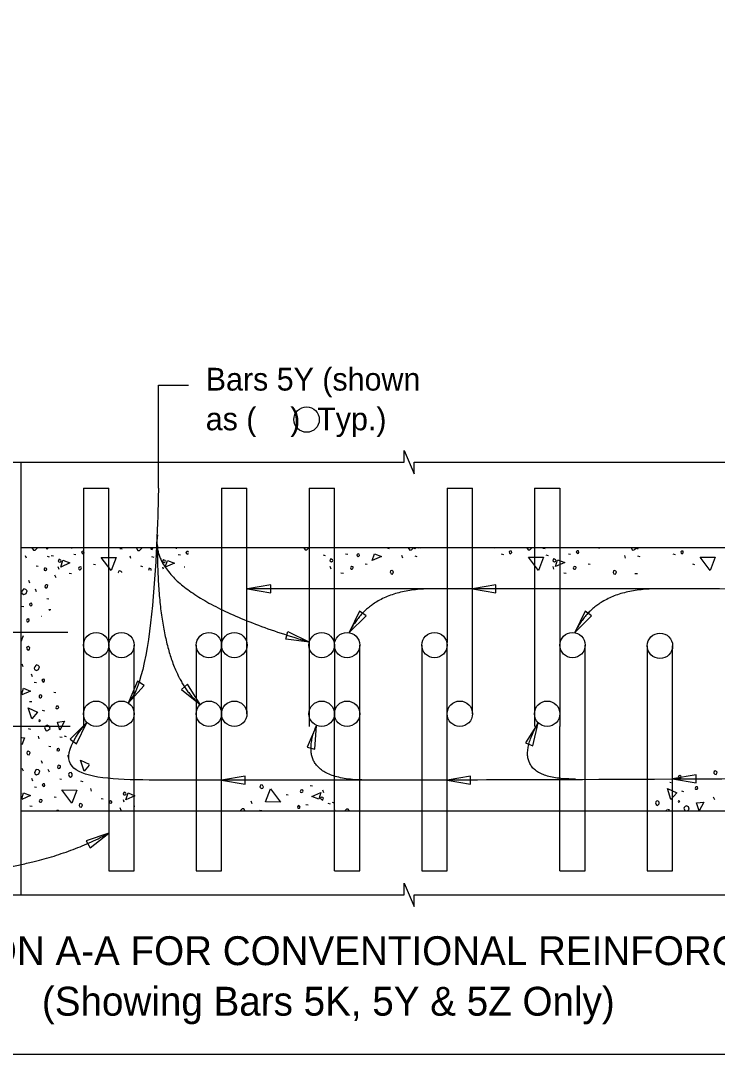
# Model space of a CAD drawing. Extents: x -21.7 to 40.7, y -0.2 to 17.4.
# Drawn here: x 6.2 to 9.289, y 3.607 to 8.188 of the extents above; entities that cross this region are included whole.
import ezdxf

# ---------------------------------------------------------------- set-up
doc = ezdxf.new("R2010")
doc.units = 0
for name, color, linetype in [('ActivePts-ConstElements', 7, 'Continuous'), ('AdhocPoint_dp', 7, 'Continuous'), ('Border', 7, 'Continuous'), ('Patterning', 7, 'Continuous'), ('PlotBorder_dp', 7, 'Continuous'), ('SheetBorder_dp', 7, 'Continuous')]:
    doc.layers.add(name, color=color, linetype=linetype)

msp = doc.modelspace()

# ---------------------------------------------------------------- linework, layer by layer
at = {"layer": 'ActivePts-ConstElements'}
msp.add_lwpolyline([(4.6468, 3.607), (25.1721, 3.607), (25.1721, 16.5801), (4.6468, 16.5801)], close=True, dxfattribs=at)
at = {"layer": 'AdhocPoint_dp'}
for p, q in [((6.4086, 5.477), (6.001, 5.477)), ((6.4188, 5.0603), (5.4676, 5.0603))]:
    msp.add_line(p, q, dxfattribs=at)
for points in [[(6.8108, 6.1166), (6.8108, 6.5728), (6.9439, 6.5728)], [(6.0632, 6.2313), (7.9006, 6.2313), (7.9006, 6.283), (7.9231, 6.2313), (7.9456, 6.1796), (7.9456, 6.2313), (9.8737, 6.2313)], [(6.0632, 4.3145), (7.9006, 4.3145), (7.9006, 4.3662), (7.9231, 4.3145), (7.9456, 4.2629), (7.9456, 4.3145), (9.8737, 4.3145)]]:
    msp.add_lwpolyline(points, dxfattribs=at)
for points in [[(7.2052, 5.6701), (7.3093, 5.6524), (7.3093, 5.6877)], [(8.2036, 5.6701), (8.3078, 5.6524), (8.3078, 5.6877)], [(7.6572, 5.4761), (7.7319, 5.5508), (7.7032, 5.5712)], [(8.6572, 5.476), (8.7319, 5.5507), (8.7032, 5.5711)], [(7.3853, 5.4807), (7.4803, 5.4345), (7.3754, 5.4468)], [(6.6764, 5.1641), (6.7477, 5.242), (6.7181, 5.2611)], [(6.9959, 5.1582), (6.9402, 5.2479), (6.9137, 5.2246)], [(6.4937, 5.078), (6.4188, 5.0036), (6.4475, 4.983)], [(7.5118, 5.0652), (7.47, 4.9683), (7.5043, 4.9599)], [(8.4952, 5.0766), (8.4391, 4.9872), (8.4717, 4.9737)], [(7.0912, 4.8226), (7.1953, 4.8049), (7.1953, 4.8402)], [(8.0911, 4.8226), (8.1952, 4.8049), (8.1952, 4.8402)], [(9.091, 4.8281), (9.1952, 4.8104), (9.1952, 4.8457)], [(6.5911, 4.5872), (6.4911, 4.5533), (6.5078, 4.5223)]]:
    msp.add_lwpolyline(points, close=True, dxfattribs=at)
for points, degree in [([(6.8108, 6.1166), (6.8082, 5.99), (6.7969, 5.2786), (6.6768, 5.1645)], 3), ([(6.807, 5.909), (6.7619, 5.6447), (7.4803, 5.4345)], 2), ([(6.8062, 5.8611), (6.8051, 5.3098), (6.9959, 5.1582)], 2), ([(9.9351, 5.669), (8.6633, 5.6701), (8.232, 5.6701), (7.2052, 5.6701)], 3), ([(8.0247, 5.6701), (7.7495, 5.6706), (7.6572, 5.4761)], 2), ([(9.0247, 5.6701), (8.7495, 5.6706), (8.6572, 5.476)], 2), ([(9.9425, 4.8297), (8.3909, 4.8226), (7.9981, 4.8226), (6.7858, 4.8226), (6.2772, 4.8226), (6.4937, 5.078)], 3), ([(7.7347, 4.8226), (7.4098, 4.8226), (7.5118, 5.0652)], 2), ([(8.6602, 4.8271), (8.3476, 4.8233), (8.4952, 5.0766)], 2), ([(5.776, 4.4087), (6.2517, 4.4054), (6.5911, 4.5872)], 2)]:
    msp.add_open_spline(points, degree=degree, dxfattribs=at)
at = {"layer": 'Border'}
for p, q in [((6.3355, 5.8186), (6.345, 5.8163)), ((6.4281, 5.8487), (6.4272, 5.8511)), ((6.4351, 5.824), (6.4451, 5.8222)), ((6.6396, 5.8493), (6.6496, 5.8476)), ((6.8911, 5.8475), (6.8904, 5.8495)), ((6.8982, 5.8228), (6.9082, 5.821)), ((7.5408, 5.8205), (7.5503, 5.8182)), ((7.6404, 5.8259), (7.6504, 5.8241)), ((7.8248, 5.8512), (7.8348, 5.8494)), ((8.3037, 5.8494), (8.3028, 5.852)), ((8.3308, 5.8247), (8.3408, 5.8229)), ((8.5153, 5.85), (8.5253, 5.8483)), ((8.5293, 5.8205), (8.5388, 5.8182)), ((8.6289, 5.8259), (8.6389, 5.8241)), ((8.7668, 5.8482), (8.7654, 5.852)), ((9.092, 5.8247), (9.102, 5.8229)), ((6.226, 5.8057), (6.2219, 5.8169)), ((6.2684, 5.7727), (6.2772, 5.771)), ((6.3173, 5.8146), (6.3267, 5.8122)), ((6.5229, 5.7798), (6.5317, 5.778)), ((6.6891, 5.8045), (6.6849, 5.8157)), ((6.7804, 5.8134), (6.7898, 5.811)), ((6.7986, 5.8175), (6.8081, 5.8151)), ((7.7282, 5.7817), (7.737, 5.7799)), ((7.8943, 5.8064), (7.8902, 5.8176)), ((7.9472, 5.8164), (7.9566, 5.8141)), ((8.7167, 5.7817), (8.7255, 5.7799)), ((8.8828, 5.8064), (8.8787, 5.8176)), ((8.9357, 5.8164), (8.9451, 5.8141)), ((9.1798, 5.7805), (9.1886, 5.7787)), ((6.3568, 5.7197), (6.352, 5.7315)), ((6.3709, 5.7563), (6.3668, 5.7675)), ((6.4151, 5.7391), (6.4257, 5.738)), ((6.7315, 5.7715), (6.7403, 5.7698)), ((6.8329, 5.7579), (6.8299, 5.7663)), ((7.5762, 5.7581), (7.5721, 5.7693)), ((7.6203, 5.741), (7.6309, 5.7398)), ((8.5647, 5.7581), (8.5606, 5.7693)), ((8.6088, 5.741), (8.6194, 5.7398)), ((8.9241, 5.7387), (8.9347, 5.7375)), ((6.2407, 5.6955), (6.236, 5.7073)), ((6.2707, 5.6573), (6.266, 5.669)), ((6.2041, 5.593), (6.2142, 5.5913)), ((6.3167, 5.6278), (6.3249, 5.6266)), ((6.2919, 5.5488), (6.2937, 5.5485)), ((6.2108, 5.3251), (6.2061, 5.3369)), ((6.2526, 5.2809), (6.2485, 5.2921)), ((6.2596, 5.2562), (6.2697, 5.2544)), ((6.3474, 5.212), (6.3563, 5.2102)), ((6.2396, 5.1714), (6.2502, 5.1702)), ((6.2956, 5.1319), (6.305, 5.1295)), ((6.2332, 5.0506), (6.2432, 5.0488)), ((6.2827, 5.0058), (6.2785, 5.017)), ((6.374, 5.0146), (6.3834, 5.0123)), ((6.3922, 5.0187), (6.4016, 5.0164)), ((6.3251, 4.9728), (6.3339, 4.971)), ((6.2974, 4.8956), (6.2927, 4.9074)), ((6.4134, 4.9198), (6.4087, 4.9316)), ((6.2119, 4.862), (6.2072, 4.8738)), ((6.3274, 4.8574), (6.3227, 4.8691)), ((6.2538, 4.8178), (6.2497, 4.829)), ((6.3734, 4.8279), (6.3816, 4.8267)), ((6.4653, 4.8185), (6.4753, 4.8167)), ((9.0784, 4.8132), (9.0849, 4.8125)), ((6.2608, 4.7931), (6.2708, 4.7914)), ((6.5148, 4.7737), (6.5107, 4.7849)), ((7.4942, 4.7959), (7.4836, 4.7971)), ((7.5384, 4.7788), (7.5425, 4.7676)), ((9.1303, 4.7742), (9.1397, 4.7718)), ((6.3486, 4.7489), (6.3575, 4.7472)), ((6.5572, 4.7407), (6.5661, 4.7389)), ((6.6597, 4.7242), (6.6556, 4.7354)), ((7.2202, 4.7305), (7.2244, 4.7193)), ((7.3864, 4.7553), (7.3776, 4.757)), ((7.592, 4.7205), (7.5826, 4.7229)), ((9.2776, 4.7353), (9.2729, 4.7471)), ((6.2408, 4.7083), (6.2514, 4.7071)), ((6.6456, 4.6877), (6.6409, 4.6995)), ((6.7039, 4.7071), (6.7064, 4.7068)), ((7.2697, 4.6857), (7.2597, 4.6875)), ((7.4742, 4.7111), (7.4642, 4.7129)), ((7.4812, 4.6864), (7.4818, 4.685)), ((7.5738, 4.7164), (7.5643, 4.7188)), ((9.0678, 4.6929), (9.0778, 4.6911))]:
    msp.add_line(p, q, dxfattribs=at)
for points in [[(6.25, 5.8518), (6.2566, 5.8411), (6.2643, 5.8417), (6.2672, 5.8446), (6.2737, 5.8511), (6.2735, 5.8517)], [(6.3173, 5.844), (6.3148, 5.8516)], [(6.3212, 5.8515), (6.3173, 5.844)], [(6.4722, 5.8281), (6.4758, 5.8246), (6.4793, 5.8269), (6.4816, 5.8305), (6.4805, 5.8364), (6.4775, 5.8369), (6.4734, 5.8364), (6.4699, 5.8328), (6.4722, 5.8281)], [(6.7134, 5.8501), (6.7197, 5.8399), (6.7274, 5.8405), (6.7303, 5.8434), (6.7368, 5.8499), (6.7367, 5.85)], [(6.7804, 5.8428), (6.7781, 5.8499)], [(6.784, 5.8499), (6.7804, 5.8428)], [(6.9444, 5.8309), (6.9435, 5.8352), (6.9406, 5.8358), (6.9365, 5.8352), (6.9329, 5.8316), (6.9353, 5.8269)], [(6.9353, 5.8269), (6.9388, 5.8234), (6.9424, 5.8258), (6.9437, 5.8278)], [(7.4563, 5.852), (7.4619, 5.843), (7.4696, 5.8435), (7.4725, 5.8465), (7.478, 5.852)], [(7.6927, 5.8163), (7.6962, 5.8127), (7.6998, 5.8151), (7.7021, 5.8186), (7.7009, 5.8245), (7.698, 5.8251), (7.6939, 5.8245), (7.6903, 5.821), (7.6927, 5.8163)], [(7.7593, 5.7952), (7.7688, 5.8259), (7.8, 5.8135), (7.7593, 5.7952)], [(7.9187, 5.852), (7.925, 5.8418), (7.9326, 5.8424), (7.9356, 5.8453), (7.9421, 5.8518), (7.942, 5.852)], [(7.9472, 5.8459), (7.9452, 5.852)], [(7.9503, 5.852), (7.9472, 5.8459)], [(7.9635, 5.8511), (7.9633, 5.852)], [(7.9694, 5.852), (7.9681, 5.8494)], [(8.3679, 5.8288), (8.3715, 5.8253), (8.375, 5.8276), (8.3774, 5.8312), (8.3762, 5.8371), (8.3732, 5.8376), (8.3691, 5.8371), (8.3656, 5.8335), (8.3679, 5.8288)], [(8.4448, 5.852), (8.4504, 5.843), (8.4581, 5.8435), (8.461, 5.8465), (8.4665, 5.852)], [(8.666, 5.83), (8.6695, 5.8265), (8.6731, 5.8288), (8.6754, 5.8323), (8.6742, 5.8382), (8.6713, 5.8388), (8.6672, 5.8382), (8.6636, 5.8347), (8.666, 5.83)], [(8.9072, 5.852), (8.9135, 5.8418), (8.9211, 5.8424), (8.9241, 5.8453), (8.9306, 5.8518), (8.9305, 5.852)], [(8.9357, 5.8459), (8.9337, 5.852)], [(8.9388, 5.852), (8.9357, 5.8459)], [(9.1291, 5.8288), (9.1326, 5.8253), (9.1361, 5.8276), (9.1385, 5.8312), (9.1373, 5.8371), (9.1344, 5.8376), (9.1303, 5.8371), (9.1267, 5.8335), (9.1291, 5.8288)], [(6.3697, 5.7892), (6.3738, 5.7886), (6.378, 5.7904), (6.3792, 5.7939), (6.3774, 5.7968), (6.3738, 5.7992), (6.3697, 5.801), (6.3674, 5.7963), (6.3662, 5.7927), (6.3697, 5.7892)], [(6.3779, 5.7668), (6.3874, 5.7975), (6.4186, 5.7851), (6.3779, 5.7668)], [(6.6013, 5.7509), (6.5565, 5.8098), (6.6231, 5.8093), (6.6013, 5.7509)], [(6.8328, 5.788), (6.8369, 5.7874), (6.8411, 5.7892), (6.8422, 5.7927), (6.8405, 5.7957), (6.8369, 5.798), (6.8328, 5.7998), (6.8304, 5.7951), (6.8293, 5.7915), (6.8328, 5.788)], [(6.841, 5.7656), (6.8504, 5.7963), (6.8817, 5.7839), (6.841, 5.7656)], [(7.575, 5.7911), (7.5791, 5.7905), (7.5833, 5.7922), (7.5844, 5.7958), (7.5827, 5.7987), (7.5791, 5.8011), (7.575, 5.8028), (7.5726, 5.7981), (7.5715, 5.7946), (7.575, 5.7911)], [(8.497, 5.7516), (8.4522, 5.8105), (8.5188, 5.81), (8.497, 5.7516)], [(8.5635, 5.7911), (8.5676, 5.7905), (8.5718, 5.7922), (8.5729, 5.7958), (8.5712, 5.7987), (8.5676, 5.8011), (8.5635, 5.8028), (8.5611, 5.7981), (8.56, 5.7946), (8.5635, 5.7911)], [(8.5717, 5.7687), (8.5811, 5.7993), (8.6124, 5.787), (8.5717, 5.7687)], [(9.2581, 5.7516), (9.2133, 5.8105), (9.2799, 5.81), (9.2581, 5.7516)], [(6.3044, 5.7533), (6.3108, 5.7515), (6.315, 5.7545), (6.3155, 5.7586), (6.3144, 5.7598), (6.3097, 5.7621), (6.3055, 5.7615), (6.3049, 5.7574), (6.3044, 5.7533)], [(6.4604, 5.755), (6.4628, 5.755), (6.4675, 5.7574), (6.4693, 5.7627), (6.4687, 5.7656), (6.464, 5.768), (6.4581, 5.7645), (6.4569, 5.7609), (6.4581, 5.7574), (6.4604, 5.755)], [(6.6479, 5.7419), (6.6484, 5.7438), (6.6455, 5.7468), (6.6402, 5.7497), (6.6349, 5.748), (6.6331, 5.7427), (6.6341, 5.7407)], [(6.7779, 5.7531), (6.778, 5.7533), (6.7786, 5.7574), (6.7775, 5.7586), (6.7727, 5.7609), (6.7686, 5.7603), (6.768, 5.7562), (6.7675, 5.7522)], [(6.9283, 5.7662), (6.927, 5.7668), (6.9256, 5.766)], [(7.6657, 5.7569), (7.6681, 5.7569), (7.6728, 5.7593), (7.6745, 5.7646), (7.674, 5.7675), (7.6692, 5.7699), (7.6634, 5.7663), (7.6622, 5.7628), (7.6634, 5.7593), (7.6657, 5.7569)], [(7.8395, 5.7422), (7.8425, 5.7369), (7.8496, 5.7357), (7.8525, 5.741), (7.8537, 5.7457), (7.8507, 5.7487), (7.8454, 5.7516), (7.8401, 5.7498), (7.8384, 5.7445), (7.8395, 5.7422)], [(8.6542, 5.7569), (8.6566, 5.7569), (8.6613, 5.7593), (8.6631, 5.7646), (8.6625, 5.7675), (8.6577, 5.7699), (8.6519, 5.7663), (8.6507, 5.7628), (8.6519, 5.7593), (8.6542, 5.7569)], [(8.828, 5.7422), (8.831, 5.7369), (8.8381, 5.7357), (8.841, 5.741), (8.8422, 5.7457), (8.8392, 5.7487), (8.8339, 5.7516), (8.8286, 5.7498), (8.8269, 5.7445), (8.828, 5.7422)], [(6.3073, 5.6797), (6.3102, 5.6743), (6.3167, 5.6749), (6.3196, 5.6791), (6.3202, 5.6855), (6.3161, 5.6873), (6.3132, 5.6879), (6.3096, 5.6867), (6.3084, 5.6855), (6.3073, 5.6797)], [(6.2065, 5.6496), (6.2142, 5.6454), (6.2242, 5.6496), (6.2283, 5.6619), (6.2224, 5.6678), (6.2148, 5.6696), (6.2113, 5.6672), (6.2071, 5.6608), (6.2042, 5.6555), (6.2065, 5.6496)], [(6.2413, 5.5972), (6.2448, 5.5936), (6.2483, 5.596), (6.2507, 5.5995), (6.2495, 5.6054), (6.2466, 5.606), (6.2424, 5.6054), (6.2389, 5.6019), (6.2413, 5.5972)], [(6.3288, 5.5746), (6.3255, 5.5789), (6.3345, 5.5788)], [(6.2295, 5.5241), (6.2318, 5.5241), (6.2366, 5.5264), (6.2383, 5.5317), (6.2377, 5.5347), (6.233, 5.5371), (6.2271, 5.5335), (6.2259, 5.53), (6.2271, 5.5264), (6.2295, 5.5241)], [(6.2006, 5.4737), (6.2037, 5.4737)], [(6.2109, 5.4614), (6.2011, 5.4352)], [(6.2267, 5.4047), (6.2296, 5.3994), (6.2367, 5.3982), (6.2396, 5.4035), (6.2408, 5.4082), (6.2379, 5.4111), (6.2326, 5.4141), (6.2273, 5.4123), (6.2255, 5.407), (6.2267, 5.4047)], [(6.262, 5.3127), (6.2697, 5.3086), (6.2797, 5.3127), (6.2838, 5.3251), (6.2779, 5.331), (6.2703, 5.3328), (6.2667, 5.3304), (6.2626, 5.3239), (6.2597, 5.3186), (6.262, 5.3127)], [(6.2968, 5.2603), (6.3003, 5.2568), (6.3038, 5.2592), (6.3062, 5.2627), (6.305, 5.2686), (6.3021, 5.2692), (6.2979, 5.2686), (6.2944, 5.265), (6.2968, 5.2603)], [(6.2045, 5.2055), (6.2119, 5.2297), (6.2431, 5.2173), (6.2046, 5.2)], [(6.285, 5.1873), (6.2873, 5.1873), (6.292, 5.1896), (6.2938, 5.1949), (6.2932, 5.1979), (6.2885, 5.2002), (6.2826, 5.1967), (6.2814, 5.1932), (6.2826, 5.1896), (6.285, 5.1873)], [(6.2491, 5.0936), (6.2332, 5.1425), (6.275, 5.1242), (6.2491, 5.0936)], [(6.358, 5.1401), (6.3651, 5.1401), (6.3687, 5.1437), (6.3669, 5.1501), (6.3592, 5.1507), (6.358, 5.1472), (6.3563, 5.1442), (6.358, 5.1401), (6.3569, 5.1413)], [(6.2821, 5.0818), (6.2885, 5.0848), (6.2862, 5.0871), (6.2821, 5.0889), (6.2803, 5.0848), (6.2821, 5.0818)], [(6.3056, 5.0535), (6.3133, 5.0412), (6.321, 5.0418), (6.3239, 5.0447), (6.3304, 5.0512), (6.3263, 5.0612), (6.318, 5.0659), (6.3121, 5.0636), (6.3074, 5.0588), (6.3056, 5.0535)], [(6.374, 5.0441), (6.3628, 5.0788), (6.394, 5.083), (6.374, 5.0441)], [(6.2048, 5.0106), (6.2167, 5.0105), (6.2048, 4.9787)], [(6.2279, 4.9416), (6.2308, 4.9363), (6.2379, 4.9351), (6.2408, 4.9404), (6.242, 4.9451), (6.2391, 4.9481), (6.2337, 4.951), (6.2284, 4.9492), (6.2267, 4.9439), (6.2279, 4.9416)], [(6.361, 4.9534), (6.3675, 4.9516), (6.3716, 4.9545), (6.3722, 4.9587), (6.371, 4.9598), (6.3663, 4.9622), (6.3622, 4.9616), (6.3616, 4.9575), (6.361, 4.9534)], [(6.4812, 4.8615), (6.4653, 4.9104), (6.5039, 4.8935)], [(6.2632, 4.8497), (6.2709, 4.8455), (6.2809, 4.8497), (6.285, 4.862), (6.2791, 4.8679), (6.2715, 4.8697), (6.2679, 4.8673), (6.2638, 4.8609), (6.2609, 4.8555), (6.2632, 4.8497)], [(6.3639, 4.8797), (6.3669, 4.8744), (6.3734, 4.875), (6.3763, 4.8792), (6.3769, 4.8856), (6.3728, 4.8874), (6.3698, 4.888), (6.3663, 4.8868), (6.3651, 4.8856), (6.3639, 4.8797)], [(6.5045, 4.889), (6.4812, 4.8615)], [(9.2745, 4.8537), (9.2775, 4.8484), (9.2845, 4.8472), (9.2875, 4.8525), (9.2887, 4.8572), (9.2857, 4.8602), (9.2804, 4.8631), (9.2751, 4.8613), (9.2733, 4.856), (9.2745, 4.8537)], [(6.4123, 4.8467), (6.4158, 4.8397), (6.4217, 4.8361), (6.4264, 4.8397), (6.4288, 4.8432), (6.4288, 4.8503), (6.4235, 4.8556), (6.417, 4.855), (6.414, 4.852), (6.4123, 4.8467)], [(9.1196, 4.8296), (9.122, 4.8296), (9.1267, 4.8319), (9.1285, 4.8372), (9.1279, 4.8402), (9.1232, 4.8425), (9.1173, 4.839), (9.1161, 4.8355), (9.1173, 4.8319), (9.1196, 4.8296)], [(6.2048, 4.7396), (6.2131, 4.7666), (6.2443, 4.7542), (6.2048, 4.7365)], [(6.2979, 4.7972), (6.3015, 4.7937), (6.305, 4.7961), (6.3074, 4.7996), (6.3062, 4.8055), (6.3032, 4.8061), (6.2991, 4.8055), (6.2956, 4.802), (6.2979, 4.7972)], [(6.427, 4.7201), (6.3822, 4.779), (6.4488, 4.7784), (6.427, 4.7201)], [(6.6585, 4.7571), (6.6627, 4.7566), (6.6668, 4.7583), (6.668, 4.7619), (6.6662, 4.7648), (6.6627, 4.7672), (6.6585, 4.7689), (6.6562, 4.7642), (6.655, 4.7607), (6.6585, 4.7571)], [(6.6667, 4.7348), (6.6762, 4.7654), (6.7064, 4.7534)], [(7.275, 4.7948), (7.2721, 4.8001), (7.265, 4.8012), (7.2621, 4.7959), (7.2609, 4.7912), (7.2639, 4.7883), (7.2692, 4.7853), (7.2745, 4.7871), (7.2762, 4.7924), (7.275, 4.7948)], [(7.308, 4.7842), (7.3528, 4.7252), (7.2862, 4.7258), (7.308, 4.7842)], [(7.4489, 4.78), (7.4465, 4.78), (7.4418, 4.7777), (7.44, 4.7724), (7.4406, 4.7694), (7.4453, 4.7671), (7.4512, 4.7706), (7.4524, 4.7741), (7.4512, 4.7777), (7.4489, 4.78)], [(7.5314, 4.7682), (7.5219, 4.7376), (7.4907, 4.75), (7.5314, 4.7682)], [(9.0837, 4.7359), (9.0678, 4.7848), (9.1097, 4.7666), (9.0837, 4.7359)], [(9.1927, 4.7824), (9.1998, 4.7824), (9.2033, 4.786), (9.2016, 4.7925), (9.1939, 4.793), (9.1927, 4.7895), (9.1909, 4.7866), (9.1927, 4.7824), (9.1915, 4.7836)], [(6.2048, 4.7627), (6.2049, 4.763), (6.2048, 4.7632)], [(6.2862, 4.7242), (6.2885, 4.7242), (6.2932, 4.7265), (6.295, 4.7318), (6.2944, 4.7348), (6.2897, 4.7371), (6.2838, 4.7336), (6.2826, 4.7301), (6.2838, 4.7265), (6.2862, 4.7242)], [(6.46, 4.7094), (6.4629, 4.7041), (6.47, 4.703), (6.4729, 4.7083), (6.4741, 4.713), (6.4712, 4.7159), (6.4659, 4.7189), (6.4606, 4.7171), (6.4588, 4.7118), (6.46, 4.7094)], [(6.5932, 4.7212), (6.5996, 4.7195), (6.6038, 4.7224), (6.6044, 4.7265), (6.6032, 4.7277), (6.5985, 4.7301), (6.5943, 4.7295), (6.5937, 4.7254), (6.5932, 4.7212)], [(6.7064, 4.7526), (6.6667, 4.7348)], [(7.5396, 4.7459), (7.5355, 4.7465), (7.5313, 4.7447), (7.5302, 4.7412), (7.5319, 4.7382), (7.5355, 4.7359), (7.5396, 4.7341), (7.5419, 4.7388), (7.5431, 4.7424), (7.5396, 4.7459)], [(9.0148, 4.7212), (9.0183, 4.7141), (9.0242, 4.7106), (9.0289, 4.7141), (9.0313, 4.7177), (9.0313, 4.7247), (9.026, 4.73), (9.0195, 4.7294), (9.0166, 4.7265), (9.0148, 4.7212)], [(9.1167, 4.7241), (9.1232, 4.7271), (9.1209, 4.7294), (9.1167, 4.7312), (9.115, 4.7271), (9.1167, 4.7241)], [(9.2086, 4.6864), (9.1974, 4.7212), (9.2287, 4.7253), (9.2086, 4.6864)], [(6.3689, 4.6838), (6.3681, 4.6871), (6.3604, 4.6876), (6.3592, 4.6841), (6.359, 4.6838)], [(7.1252, 4.685), (7.1265, 4.6875)], [(7.131, 4.6859), (7.1313, 4.685)], [(7.1959, 4.685), (7.1896, 4.6952), (7.1819, 4.6946), (7.179, 4.6916), (7.1725, 4.6852), (7.1726, 4.685)], [(7.4371, 4.707), (7.4336, 4.7105), (7.43, 4.7081), (7.4277, 4.7046), (7.4288, 4.6987), (7.4318, 4.6981), (7.4359, 4.6987), (7.4394, 4.7022), (7.4371, 4.707)], [(7.5889, 4.685), (7.592, 4.6911)], [(7.592, 4.6911), (7.594, 4.685)], [(7.6583, 4.685), (7.6527, 4.694), (7.645, 4.6934), (7.6421, 4.6905), (7.6366, 4.685)], [(9.0635, 4.6905), (9.0608, 4.6853)], [(9.1579, 4.6864), (9.1586, 4.687), (9.1651, 4.6935), (9.1609, 4.7035), (9.1527, 4.7082), (9.1468, 4.7059), (9.1421, 4.7012), (9.1403, 4.6959)], [(9.1403, 4.6959), (9.1462, 4.6864)]]:
    msp.add_lwpolyline(points, dxfattribs=at)
at = {"layer": 'Patterning'}
for centre in [(7.4681, 6.4204), (6.5348, 5.4207), (6.6473, 5.4207), (7.0348, 5.4207), (7.1474, 5.4207), (7.5348, 5.4207), (7.6473, 5.4207), (8.0349, 5.4207), (8.6473, 5.4207), (9.0349, 5.4177), (9.0349, 5.4177), (6.5348, 5.1166), (6.6473, 5.1166), (7.0348, 5.1166), (7.1473, 5.1166), (7.1473, 5.1166), (7.5348, 5.1166), (7.6473, 5.1166), (8.1475, 5.1166), (8.5348, 5.1166)]:
    msp.add_circle(centre, 0.0563, dxfattribs=at)
at = {"layer": 'PlotBorder_dp'}
for p, q in [((6.2005, 6.2313), (6.2005, 4.3145)), ((9.7088, 5.852), (6.2005, 5.852)), ((9.7088, 4.6853), (6.2005, 4.6853))]:
    msp.add_line(p, q, dxfattribs=at)
at = {"layer": 'SheetBorder_dp'}
for p, q in [((6.4786, 6.1166), (6.5911, 6.1166)), ((7.0911, 6.1166), (7.2036, 6.1166)), ((7.4786, 6.1166), (7.5911, 6.1166)), ((8.0912, 6.1166), (8.2036, 6.1166)), ((8.4786, 6.1166), (8.5911, 6.1166)), ((6.5911, 4.4207), (6.7036, 4.4207)), ((6.9786, 4.4207), (7.0911, 4.4207)), ((7.5911, 4.4207), (7.7036, 4.4207)), ((7.9786, 4.4207), (8.0911, 4.4207)), ((8.5911, 4.4207), (8.7036, 4.4207)), ((8.9786, 4.4207), (9.0911, 4.4207))]:
    msp.add_line(p, q, dxfattribs=at)
for points in [[(6.4786, 6.1166), (6.4786, 5.0603)], [(6.5911, 5.4249), (6.5911, 6.1166)], [(7.0911, 6.1166), (7.0911, 5.4353)], [(7.2036, 5.1166), (7.2036, 6.1166)], [(7.4786, 6.1166), (7.4786, 5.0603)], [(7.5911, 5.4249), (7.5911, 6.1166)], [(8.0912, 6.1166), (8.0912, 5.4322)], [(8.2036, 5.1166), (8.2036, 6.1166)], [(8.4786, 6.1166), (8.4786, 5.0603)], [(8.5911, 6.1166), (8.5911, 5.0603)], [(6.5911, 5.4249), (6.5911, 5.102)], [(6.7036, 4.4207), (6.7036, 5.4207)], [(6.9786, 5.4207), (6.9786, 4.4207)], [(7.0911, 4.4207), (7.0911, 5.4353)], [(7.5911, 5.4249), (7.5911, 5.102)], [(7.7036, 4.4207), (7.7036, 5.4207)], [(7.9786, 5.4207), (7.9786, 4.4207)], [(8.0911, 4.4207), (8.0911, 5.4322)], [(8.7036, 4.4207), (8.7036, 5.4207)], [(8.9786, 5.4177), (8.9786, 4.4207)], [(9.0911, 4.4207), (9.0911, 5.4177)], [(6.5911, 5.102), (6.5911, 4.4207)], [(7.5911, 4.4207), (7.5911, 5.102)], [(8.5911, 4.4207), (8.5911, 5.0603)]]:
    msp.add_lwpolyline(points, dxfattribs=at)

# ---------------------------------------------------------------- texts
at = {"layer": 'AdhocPoint_dp'}
for s, height, p in [('Bars 5Y (shown ', 0.1008, (7.0208, 6.549)), ('as (    )  Typ.)', 0.1008, (7.0208, 6.373)), ('SECTION A-A FOR CONVENTIONAL REINFORCING', 0.128, (5.546, 4.0024)), ('(Showing Bars 5K, 5Y & 5Z Only)', 0.128, (6.2942, 3.7784))]:
    msp.add_text(s, height=height, dxfattribs=at).set_placement(p)

doc.saveas('drawing.dxf')
